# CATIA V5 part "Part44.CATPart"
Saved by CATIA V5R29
Part number: moving part
Revision: ANY
Definition: UNKNOWN
Nomenclature: moving part
Source: Unknown
Bounding box of the stored display mesh (mm): x 2 to 39.989, y 0 to 217, z -20 to 20
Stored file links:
  C:\Users\Administrator\Desktop\프로젝트\Gripper\Part44.CATPart
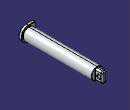
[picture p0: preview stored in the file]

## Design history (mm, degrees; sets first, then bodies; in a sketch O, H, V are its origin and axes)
Body1 "Fillet5" (main body)
  Solid1: solid without history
